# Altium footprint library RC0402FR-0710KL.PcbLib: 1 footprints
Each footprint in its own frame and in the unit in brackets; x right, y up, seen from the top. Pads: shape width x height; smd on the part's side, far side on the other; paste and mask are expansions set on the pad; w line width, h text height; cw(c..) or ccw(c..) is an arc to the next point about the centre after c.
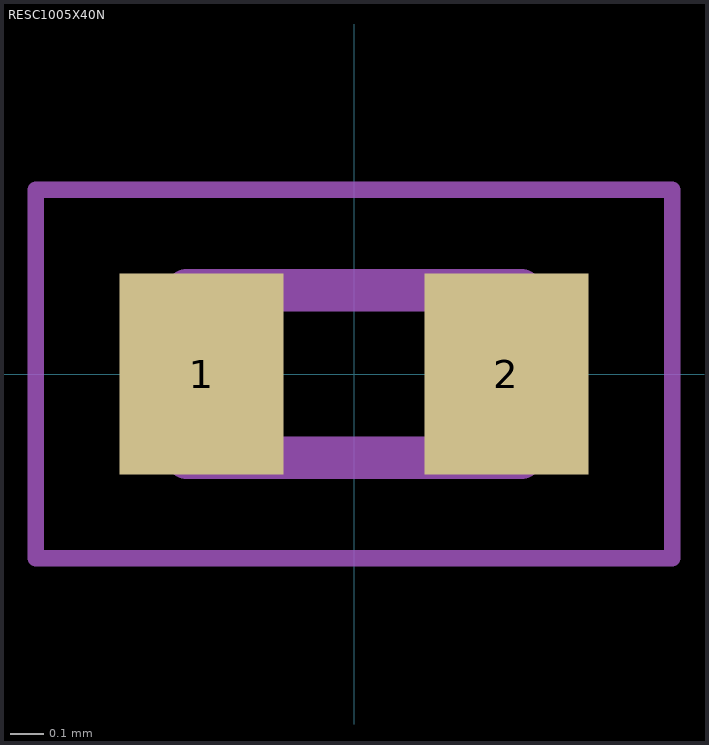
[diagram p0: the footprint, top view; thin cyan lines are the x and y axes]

## RESC1005X40N [mm]
height 0.4
pads (2):
  rect 0.49x0.6 smd paste+0 mask+0.102: 1(-0.455,0) 2(0.455,0)
Assembly Top:
  lines w0.127: -0.5,-0.25 -0.5,0.25 0.5,0.25 0.5,-0.25 -0.5,-0.25
Courtyard Top:
  lines w0.05: -0.95,-0.55 -0.95,0.55 0.95,0.55 0.95,-0.55 -0.95,-0.55
3D body "step_temp.STEP": height 0.4, standoff 0, extent -0.5,-0.25 0.5,0.25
